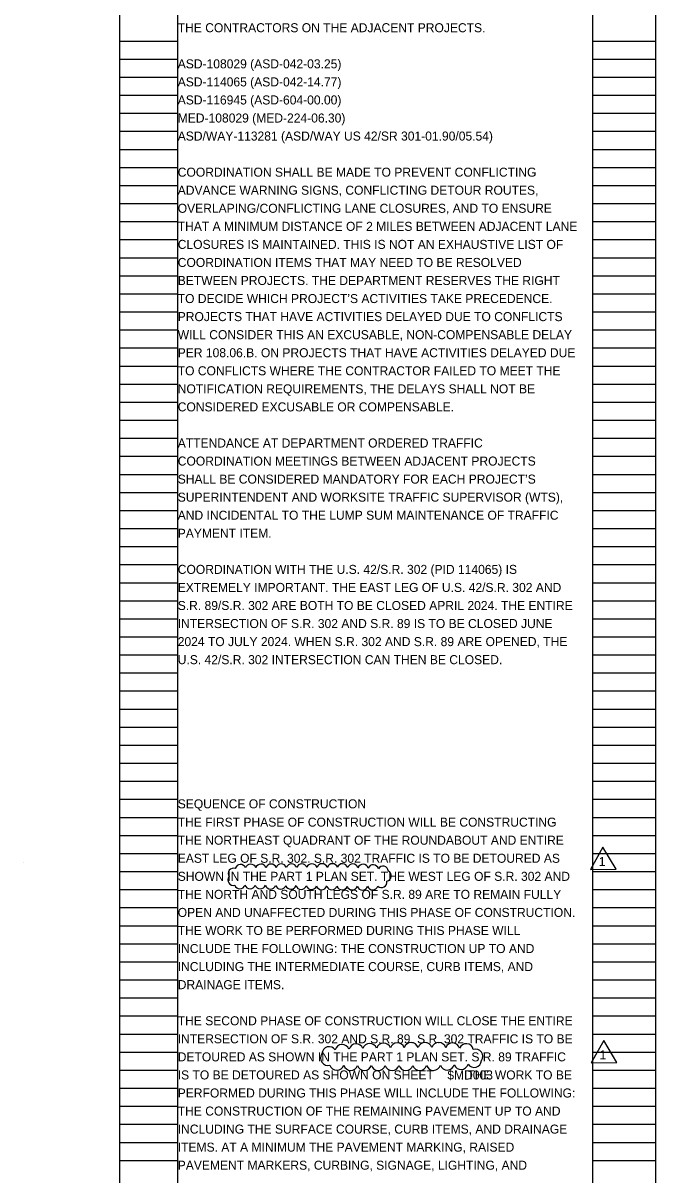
# Model space of a CAD drawing. Extents: x -9 to 32, y -122 to 20.
# Drawn here: x -0.28 to 9.54, y -86.16 to -68.3 of the extents above; entities that cross this region are included whole.
import ezdxf

# ---------------------------------------------------------------- set-up
doc = ezdxf.new("R2010")
doc.units = 0
for name, color, linetype in [('SC_Scratch1', 7, 'Continuous'), ('SC_Scratch2', 7, 'Continuous'), ('SH_Text', 7, 'Continuous')]:
    doc.layers.add(name, color=color, linetype=linetype)

msp = doc.modelspace()

# ---------------------------------------------------------------- linework, layer by layer
at = {"layer": 'SC_Scratch1'}
for p, q in [((1.216, -80.334), (1.216, -60.174)), ((2.116, -80.334), (2.116, -60.174)), ((8.556, -80.334), (8.556, -60.174)), ((9.536, -80.334), (9.536, -60.174)), ((1.216, -68.574), (2.116, -68.574)), ((8.556, -68.574), (9.536, -68.574)), ((1.216, -68.854), (2.116, -68.854)), ((8.556, -68.854), (9.536, -68.854)), ((1.216, -69.134), (2.116, -69.134)), ((8.556, -69.134), (9.536, -69.134)), ((1.216, -69.414), (2.116, -69.414)), ((8.556, -69.414), (9.536, -69.414)), ((1.216, -69.694), (2.116, -69.694)), ((8.556, -69.694), (9.536, -69.694)), ((1.216, -69.974), (2.116, -69.974)), ((8.556, -69.974), (9.536, -69.974)), ((1.216, -70.254), (2.116, -70.254)), ((8.556, -70.254), (9.536, -70.254)), ((1.216, -70.534), (2.116, -70.534)), ((8.556, -70.534), (9.536, -70.534)), ((1.216, -70.814), (2.116, -70.814)), ((8.556, -70.814), (9.536, -70.814)), ((1.216, -71.094), (2.116, -71.094)), ((8.556, -71.094), (9.536, -71.094)), ((1.216, -71.374), (2.116, -71.374)), ((8.556, -71.374), (9.536, -71.374)), ((1.216, -71.654), (2.116, -71.654)), ((8.556, -71.654), (9.536, -71.654)), ((1.216, -71.934), (2.116, -71.934)), ((8.556, -71.934), (9.536, -71.934)), ((1.216, -72.214), (2.116, -72.214)), ((8.556, -72.214), (9.536, -72.214)), ((1.216, -72.494), (2.116, -72.494)), ((8.556, -72.494), (9.536, -72.494)), ((1.216, -72.774), (2.116, -72.774)), ((8.556, -72.774), (9.536, -72.774)), ((1.216, -73.054), (2.116, -73.054)), ((8.556, -73.054), (9.536, -73.054)), ((1.216, -73.334), (2.116, -73.334)), ((8.556, -73.334), (9.536, -73.334)), ((1.216, -73.614), (2.116, -73.614)), ((8.556, -73.614), (9.536, -73.614)), ((1.216, -73.894), (2.116, -73.894)), ((8.556, -73.894), (9.536, -73.894)), ((1.216, -74.174), (2.116, -74.174)), ((8.556, -74.174), (9.536, -74.174)), ((1.216, -74.454), (2.116, -74.454)), ((8.556, -74.454), (9.536, -74.454)), ((1.216, -74.734), (2.116, -74.734)), ((8.556, -74.734), (9.536, -74.734)), ((1.216, -75.014), (2.116, -75.014)), ((8.556, -75.014), (9.536, -75.014)), ((1.216, -75.294), (2.116, -75.294)), ((8.556, -75.294), (9.536, -75.294)), ((1.216, -75.574), (2.116, -75.574)), ((8.556, -75.574), (9.536, -75.574)), ((1.216, -75.854), (2.116, -75.854)), ((8.556, -75.854), (9.536, -75.854)), ((1.216, -76.134), (2.116, -76.134)), ((8.556, -76.134), (9.536, -76.134)), ((1.216, -76.414), (2.116, -76.414)), ((8.556, -76.414), (9.536, -76.414)), ((1.216, -76.694), (2.116, -76.694)), ((8.556, -76.694), (9.536, -76.694)), ((1.216, -76.974), (2.116, -76.974)), ((8.556, -76.974), (9.536, -76.974)), ((1.216, -77.254), (2.116, -77.254)), ((8.556, -77.254), (9.536, -77.254)), ((1.216, -77.534), (2.116, -77.534)), ((8.556, -77.534), (9.536, -77.534)), ((1.216, -77.814), (2.116, -77.814)), ((8.556, -77.814), (9.536, -77.814)), ((1.216, -78.094), (2.116, -78.094)), ((8.556, -78.094), (9.536, -78.094)), ((1.216, -78.374), (2.116, -78.374)), ((8.556, -78.374), (9.536, -78.374)), ((1.216, -78.654), (2.116, -78.654)), ((8.556, -78.654), (9.536, -78.654)), ((1.216, -78.934), (2.116, -78.934)), ((8.556, -78.934), (9.536, -78.934)), ((1.216, -79.214), (2.116, -79.214)), ((8.556, -79.214), (9.536, -79.214)), ((1.216, -79.494), (2.116, -79.494)), ((8.556, -79.494), (9.536, -79.494)), ((1.216, -79.774), (2.116, -79.774)), ((8.556, -79.774), (9.536, -79.774)), ((1.216, -80.054), (2.116, -80.054)), ((8.556, -80.054), (9.536, -80.054)), ((1.216, -80.334), (2.116, -80.334)), ((1.216, -100.494), (1.216, -80.334)), ((1.216, -80.334), (2.116, -80.334)), ((2.116, -100.494), (2.116, -80.334)), ((8.556, -80.334), (9.536, -80.334)), ((8.556, -100.494), (8.556, -80.334)), ((8.556, -80.334), (9.536, -80.334)), ((9.536, -100.494), (9.536, -80.334)), ((1.216, -80.614), (2.116, -80.614)), ((8.556, -80.614), (9.536, -80.614)), ((1.216, -80.894), (2.116, -80.894)), ((8.556, -80.894), (9.536, -80.894)), ((1.216, -81.174), (2.116, -81.174)), ((8.556, -81.174), (9.536, -81.174)), ((-0.284, -81.314), (-0.284, -81.314)), ((1.216, -81.454), (2.116, -81.454)), ((8.556, -81.454), (9.536, -81.454)), ((1.216, -81.734), (2.116, -81.734)), ((8.556, -81.734), (9.536, -81.734)), ((1.216, -82.014), (2.116, -82.014)), ((8.556, -82.014), (9.536, -82.014)), ((1.216, -82.294), (2.116, -82.294)), ((8.556, -82.294), (9.536, -82.294)), ((1.216, -82.574), (2.116, -82.574)), ((8.556, -82.574), (9.536, -82.574)), ((1.216, -82.854), (2.116, -82.854)), ((8.556, -82.854), (9.536, -82.854)), ((1.216, -83.134), (2.116, -83.134)), ((8.556, -83.134), (9.536, -83.134)), ((1.216, -83.414), (2.116, -83.414)), ((8.556, -83.414), (9.536, -83.414)), ((1.216, -83.694), (2.116, -83.694)), ((8.556, -83.694), (9.536, -83.694)), ((1.216, -83.974), (2.116, -83.974)), ((8.556, -83.974), (9.536, -83.974)), ((1.216, -84.254), (2.116, -84.254)), ((8.556, -84.254), (9.536, -84.254)), ((1.216, -84.534), (2.116, -84.534)), ((8.556, -84.534), (9.536, -84.534)), ((1.216, -84.814), (2.116, -84.814)), ((8.556, -84.814), (9.536, -84.814)), ((1.216, -85.094), (2.116, -85.094)), ((8.556, -85.094), (9.536, -85.094)), ((1.216, -85.374), (2.116, -85.374)), ((8.556, -85.374), (9.536, -85.374)), ((1.216, -85.654), (2.116, -85.654)), ((8.556, -85.654), (9.536, -85.654)), ((1.216, -85.934), (2.116, -85.934)), ((8.556, -85.934), (9.536, -85.934))]:
    msp.add_line(p, q, dxfattribs=at)
at = {"layer": 'SC_Scratch2'}
for points in [[(8.918, -81.417), (8.713, -81.075), (8.519, -81.423)], [(8.93, -84.415), (8.725, -84.072), (8.531, -84.42)]]:
    msp.add_lwpolyline(points, close=True, dxfattribs=at)
for centre, radius, start, end in [((2.982, -81.484), 0.0831, 70.5367, 215.5367), ((3.09, -81.427), 0.0832, 20.2274, 165.2274), ((3.248, -81.422), 0.0831, 18.0991, 163.0991), ((3.406, -81.421), 0.0831, 17.969, 162.969), ((3.565, -81.42), 0.0831, 17.9078, 162.9078), ((3.723, -81.419), 0.0831, 17.8701, 162.8701), ((3.882, -81.418), 0.0831, 17.844, 162.844), ((4.04, -81.417), 0.0831, 17.8244, 162.8244), ((4.199, -81.416), 0.0831, 17.8089, 162.8089), ((4.357, -81.415), 0.0831, 17.654, 162.654), ((4.516, -81.415), 0.0831, 17.3233, 162.3233), ((4.674, -81.416), 0.0831, 16.887, 161.887), ((4.833, -81.419), 0.0831, 16.273, 161.273), ((4.991, -81.424), 0.0831, 15.3135, 160.3135), ((5.148, -81.432), 0.0831, 13.469, 158.469), ((5.301, -81.454), 0.0831, 5.1464, 150.1464), ((5.347, -81.521), 0.0831, 278.7561, 63.7561), ((2.978, -81.585), 0.0831, 140.3475, 285.3475), ((5.278, -81.619), 0.0831, 225.8358, 10.8358), ((3.079, -81.64), 0.0831, 198.1284, 343.1284), ((3.238, -81.639), 0.0831, 197.1959, 342.1959), ((3.397, -81.64), 0.0831, 196.9786, 341.9786), ((3.556, -81.642), 0.0831, 196.8644, 341.8644), ((3.714, -81.644), 0.0831, 196.7909, 341.7909), ((3.873, -81.646), 0.0831, 196.7386, 341.7386), ((4.031, -81.648), 0.0831, 196.7026, 341.7026), ((4.19, -81.65), 0.0831, 196.7273, 341.7273), ((4.348, -81.652), 0.0831, 196.7793, 341.7793), ((4.507, -81.654), 0.0831, 196.8482, 341.8482), ((4.666, -81.656), 0.0831, 196.9457, 341.9457), ((4.824, -81.657), 0.0831, 197.0995, 342.0995), ((4.982, -81.658), 0.0831, 197.4023, 342.4023), ((5.14, -81.656), 0.0831, 199.0668, 344.0668), ((4.668, -84.248), 0.112, 20.6146, 165.6146), ((4.882, -84.238), 0.112, 19.6019, 164.6019), ((5.096, -84.231), 0.112, 19.0941, 164.0941), ((5.31, -84.226), 0.112, 18.774, 163.774), ((5.524, -84.221), 0.112, 18.5438, 163.5438), ((5.738, -84.218), 0.112, 18.1837, 163.1837), ((5.952, -84.217), 0.112, 17.6225, 162.6225), ((6.166, -84.218), 0.112, 16.8019, 161.8019), ((6.38, -84.223), 0.112, 15.4276, 160.4276), ((6.592, -84.236), 0.112, 12.2806, 157.2806), ((4.443, -84.348), 0.112, 142.6658, 287.6658), ((4.466, -84.282), 0.112, 33.6523, 178.6523), ((6.737, -84.319), 0.112, 323.6471, 108.6471), ((4.585, -84.423), 0.112, 196.3927, 341.3927), ((4.799, -84.426), 0.112, 197.1252, 342.1252), ((5.013, -84.427), 0.112, 197.3014, 342.3014), ((5.227, -84.427), 0.112, 197.3942, 342.3942), ((5.442, -84.428), 0.112, 197.454, 342.454), ((5.656, -84.428), 0.112, 197.5217, 342.5217), ((5.87, -84.427), 0.112, 197.8285, 342.8285), ((6.084, -84.425), 0.112, 198.323, 343.323), ((6.298, -84.42), 0.112, 199.1057, 344.1057), ((6.511, -84.412), 0.112, 200.657, 345.657), ((6.716, -84.38), 0.112, 212.0393, 357.0393)]:
    msp.add_arc(centre, radius, start, end, dxfattribs=at)

# ---------------------------------------------------------------- texts
for p in [(8.648, -81.369), (8.66, -84.366)]:
    msp.add_text('1', height=0.14, dxfattribs=at).set_placement(p)
at = {"layer": 'SH_Text'}
for s, p in [('THE CONTRACTORS ON THE ADJACENT PROJECTS. ', (2.116, -68.438)), ('ASD-108029 (ASD-042-03.25)', (2.116, -68.998)), ('ASD-114065 (ASD-042-14.77)', (2.116, -69.278)), ('ASD-116945 (ASD-604-00.00)', (2.116, -69.558)), ('MED-108029 (MED-224-06.30)', (2.116, -69.838)), ('ASD/WAY-113281 (ASD/WAY US 42/SR 301-01.90/05.54)', (2.116, -70.118)), ('COORDINATION SHALL BE MADE TO PREVENT CONFLICTING ', (2.116, -70.678)), ('ADVANCE WARNING SIGNS, CONFLICTING DETOUR ROUTES, ', (2.116, -70.958)), ('OVERLAPING/CONFLICTING LANE CLOSURES, AND TO ENSURE ', (2.116, -71.238)), ('THAT A MINIMUM DISTANCE OF 2 MILES BETWEEN ADJACENT LANE ', (2.116, -71.518)), ('CLOSURES IS MAINTAINED. THIS IS NOT AN EXHAUSTIVE LIST OF ', (2.116, -71.798)), ('COORDINATION ITEMS THAT MAY NEED TO BE RESOLVED ', (2.116, -72.078)), ('BETWEEN PROJECTS. THE DEPARTMENT RESERVES THE RIGHT ', (2.116, -72.358)), ('TO DECIDE WHICH PROJECT’S ACTIVITIES TAKE PRECEDENCE. ', (2.116, -72.638)), ('PROJECTS THAT HAVE ACTIVITIES DELAYED DUE TO CONFLICTS ', (2.116, -72.918)), ('WILL CONSIDER THIS AN EXCUSABLE, NON-COMPENSABLE DELAY ', (2.116, -73.198)), ('PER 108.06.B. ON PROJECTS THAT HAVE ACTIVITIES DELAYED DUE ', (2.116, -73.478)), ('TO CONFLICTS WHERE THE CONTRACTOR FAILED TO MEET THE ', (2.116, -73.758)), ('NOTIFICATION REQUIREMENTS, THE DELAYS SHALL NOT BE ', (2.116, -74.038)), ('CONSIDERED EXCUSABLE OR COMPENSABLE.', (2.116, -74.318)), ('ATTENDANCE AT DEPARTMENT ORDERED TRAFFIC ', (2.116, -74.878)), ('COORDINATION MEETINGS BETWEEN ADJACENT PROJECTS ', (2.116, -75.158)), ('SHALL BE CONSIDERED MANDATORY FOR EACH PROJECT’S ', (2.116, -75.438)), ('SUPERINTENDENT AND WORKSITE TRAFFIC SUPERVISOR (WTS), ', (2.116, -75.718)), ('AND INCIDENTAL TO THE LUMP SUM MAINTENANCE OF TRAFFIC ', (2.116, -75.998)), ('PAYMENT ITEM.', (2.116, -76.278)), ('COORDINATION WITH THE U.S. 42/S.R. 302 (PID 114065) IS ', (2.116, -76.838)), ('EXTREMELY IMPORTANT. THE EAST LEG OF U.S. 42/S.R. 302 AND ', (2.116, -77.118)), ('S.R. 89/S.R. 302 ARE BOTH TO BE CLOSED APRIL 2024. THE ENTIRE ', (2.116, -77.398)), ('INTERSECTION OF S.R. 302 AND S.R. 89 IS TO BE CLOSED JUNE ', (2.116, -77.678)), ('2024 TO JULY 2024. WHEN S.R. 302 AND S.R. 89 ARE OPENED, THE ', (2.116, -77.958)), ('U.S. 42/S.R. 302 INTERSECTION CAN THEN BE CLOSED. ', (2.116, -78.238)), ('SEQUENCE OF CONSTRUCTION', (2.116, -80.474)), ('THE FIRST PHASE OF CONSTRUCTION WILL BE CONSTRUCTING ', (2.116, -80.758)), ('THE NORTHEAST QUADRANT OF THE ROUNDABOUT AND ENTIRE ', (2.116, -81.038)), ('EAST LEG OF S.R. 302. S.R. 302 TRAFFIC IS TO BE DETOURED AS ', (2.116, -81.318)), ('SHOWN IN THE PART 1 PLAN SET. THE WEST LEG OF S.R. 302 AND ', (2.116, -81.598)), ('THE NORTH AND SOUTH LEGS OF S.R. 89 ARE TO REMAIN FULLY ', (2.116, -81.878)), ('OPEN AND UNAFFECTED DURING THIS PHASE OF CONSTRUCTION. ', (2.116, -82.158)), ('THE WORK TO BE PERFORMED DURING THIS PHASE WILL ', (2.116, -82.438)), ('INCLUDE THE FOLLOWING: THE CONSTRUCTION UP TO AND ', (2.116, -82.718)), ('INCLUDING THE INTERMEDIATE COURSE, CURB ITEMS, AND ', (2.116, -82.998)), ('DRAINAGE ITEMS. ', (2.116, -83.278)), ('THE SECOND PHASE OF CONSTRUCTION WILL CLOSE THE ENTIRE ', (2.116, -83.838)), ('INTERSECTION OF S.R. 302 AND S.R. 89. S.R. 302 TRAFFIC IS TO BE ', (2.116, -84.118)), ('DETOURED AS SHOWN IN THE PART 1 PLAN SET. S.R. 89 TRAFFIC ', (2.116, -84.398)), ('IS TO BE DETOURED AS SHOWN ON SHEET        . THE WORK TO BE ', (2.116, -84.678)), ('$MD003', (6.299, -84.679)), ('PERFORMED DURING THIS PHASE WILL INCLUDE THE FOLLOWING: ', (2.116, -84.958)), ('THE CONSTRUCTION OF THE REMAINING PAVEMENT UP TO AND ', (2.116, -85.238)), ('INCLUDING THE SURFACE COURSE, CURB ITEMS, AND DRAINAGE ', (2.116, -85.518)), ('ITEMS. AT A MINIMUM THE PAVEMENT MARKING, RAISED ', (2.116, -85.798)), ('PAVEMENT MARKERS, CURBING, SIGNAGE, LIGHTING, AND ', (2.116, -86.078))]:
    msp.add_text(s, height=0.14, dxfattribs=at).set_placement(p)

doc.saveas('drawing.dxf')
